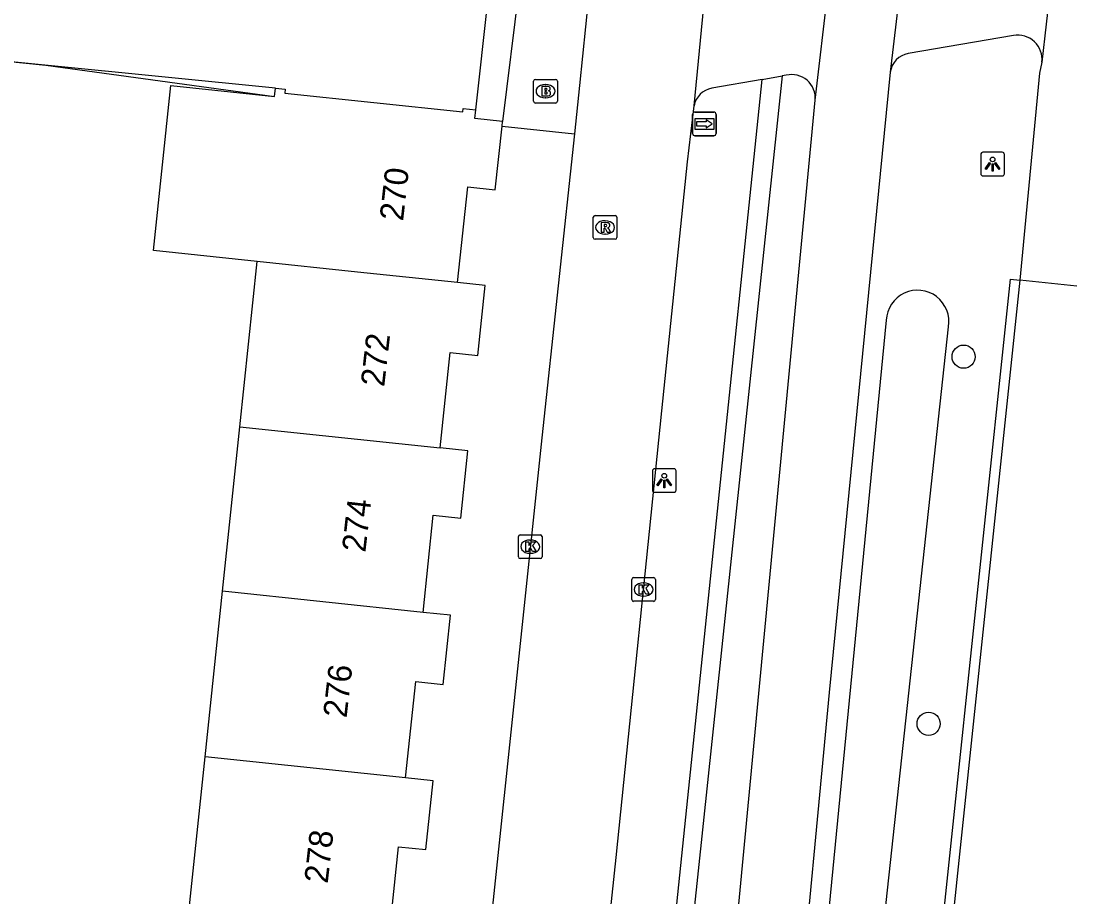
# Model space of a CAD drawing. Extents: x 161486 to 162249, y 379484 to 380829.
# Drawn here: x 162192.42 to 162236.98, y 380606.39 to 380643.33 of the extents above; entities that cross this region are included whole.
import ezdxf

# ---------------------------------------------------------------- set-up
doc = ezdxf.new("R2010")
doc.units = 0
for name, color, linetype in [('IMGEO_Berm_open', 7, 'Continuous'), ('IMGEO_Boom', 7, 'Continuous'), ('IMGEO_Brandkraan', 7, 'Continuous'), ('IMGEO_Fietspad_gesloten', 7, 'Continuous'), ('IMGEO_Fietspad_open', 7, 'Continuous'), ('IMGEO_Haag', 7, 'Continuous'), ('IMGEO_Kolk', 7, 'Continuous'), ('IMGEO_Lichtpunt', 7, 'Continuous'), ('IMGEO_Muur', 7, 'Continuous'), ('IMGEO_Pand', 7, 'Continuous'), ('IMGEO_Pand_nummerreeks', 7, 'Continuous'), ('IMGEO_Rijbaan_lokaal_gesloten', 7, 'Continuous'), ('IMGEO_Rijbaan_lokaal_open', 7, 'Continuous'), ('IMGEO_Rioolput', 7, 'Continuous'), ('IMGEO_Voetpad_open', 7, 'Continuous'), ('IMGEO_Waterloop', 7, 'Continuous'), ('IMGEO_Wegwijzer', 7, 'Continuous')]:
    doc.layers.add(name, color=color, linetype=linetype)

msp = doc.modelspace()

# ---------------------------------------------------------------- linework, layer by layer
at = {"layer": 'IMGEO_Berm_open'}
msp.add_lwpolyline([(162234.885, 380513.834), (162234.485, 380513.815), (162233.282, 380522.077), (162233.255, 380522.263), (162230.376, 380540.774), (162229.367, 380548.085), (162228.73, 380555.438), (162228.472, 380564.942), (162228.634, 380574.447), (162229.215, 380583.936), (162230.258, 380595.154), (162234.178, 380632.445), (162234.565, 380632.408)], dxfattribs=at)
at = {"layer": 'IMGEO_Boom'}
for centre in [(162232.199, 380629.179), (162230.723, 380613.693)]:
    msp.add_circle(centre, 0.489, dxfattribs=at)
at = {"layer": 'IMGEO_Brandkraan'}
for p, q in [((162214.05, 380639.952), (162214.05, 380640.804)), ((162214.125, 380640.878), (162214.977, 380640.878)), ((162214.538, 380640.658), (162214.563, 380640.658)), ((162215.051, 380640.804), (162215.051, 380639.952)), ((162214.977, 380639.878), (162214.125, 380639.878)), ((162214.561, 380640.098), (162214.536, 380640.098))]:
    msp.add_line(p, q, dxfattribs=at)
for points in [[(162214.05, 380639.952), (162214.05, 380640.804)], [(162214.125, 380640.878), (162214.977, 380640.878)], [(162214.398, 380640.578), (162214.398, 380640.178), (162214.611, 380640.178)], [(162214.629, 380640.578), (162214.398, 380640.578)], [(162215.051, 380640.804), (162215.051, 380639.952)], [(162214.577, 380640.497), (162214.523, 380640.497), (162214.523, 380640.421)], [(162214.523, 380640.421), (162214.576, 380640.421)], [(162214.585, 380640.345), (162214.523, 380640.345), (162214.523, 380640.264)], [(162214.523, 380640.264), (162214.585, 380640.264)], [(162214.977, 380639.878), (162214.125, 380639.878)]]:
    msp.add_lwpolyline(points, dxfattribs=at)
for centre, radius, start, end in [((162214.127, 380640.802), 0.0765, 91.552, 178.448), ((162214.127, 380640.802), 0.0765, 91.552, 178.448), ((162214.633, 380640.433), 0.145, 59.4692, 91.5367), ((162214.975, 380640.802), 0.0765, 1.552, 88.448), ((162214.975, 380640.802), 0.0765, 1.552, 88.448), ((162214.578, 380640.459), 0.0379, 267.8285, 90.9355), ((162214.586, 380640.304), 0.0404, 269.8759, 90.5077), ((162214.617, 380640.429), 0.251, 268.6676, 293.5347), ((162214.658, 380640.48), 0.0922, 285.5137, 58.1501), ((162214.663, 380640.288), 0.105, 301.3115, 78.989), ((162214.127, 380639.954), 0.0765, 181.552, 268.448), ((162214.127, 380639.954), 0.0765, 181.552, 268.448), ((162214.975, 380639.954), 0.0765, 271.552, 358.448), ((162214.975, 380639.954), 0.0765, 271.552, 358.448)]:
    msp.add_arc(centre, radius, start, end, dxfattribs=at)
for centre, major_axis, ratio, start_param, end_param in [((162214.537, 380640.378), (-0.387, 0.002), 0.722429, 4.712389, 7.853982), ((162214.562, 380640.378), (-0.39, 0.002), 0.717154, 1.570796, 4.712389)]:
    msp.add_ellipse(centre, major_axis=major_axis, ratio=ratio, start_param=start_param, end_param=end_param, dxfattribs=at)
at = {"layer": 'IMGEO_Fietspad_gesloten'}
for points in [[(162229.656, 380645.947), (162229.101, 380641.182)], [(162225.936, 380639.994), (162226.483, 380644.682)], [(162229.101, 380641.182), (162226.52, 380615.007), (162223.737, 380585.536)], [(162220.785, 380585.791), (162225.936, 380639.994)]]:
    msp.add_lwpolyline(points, dxfattribs=at)
at = {"layer": 'IMGEO_Fietspad_open'}
for points in [[(162234.304, 380642.732), (162229.862, 380641.971)], [(162223.699, 380640.873), (162224.538, 380641.02)], [(162224.713, 380641.051), (162224.538, 380641.02)], [(162223.699, 380640.873), (162221.566, 380640.501)]]:
    msp.add_lwpolyline(points, dxfattribs=at)
for centre, radius, start, end in [((162234.48, 380641.714), 1.033, 353.8878, 99.7979), ((162230.04, 380641.038), 0.95, 100.8127, 171.2572), ((162224.946, 380640.085), 0.994, 354.7527, 103.5756), ((162221.732, 380639.586), 0.93, 100.3017, 169.0038)]:
    msp.add_arc(centre, radius, start, end, dxfattribs=at)
at = {"layer": 'IMGEO_Haag'}
msp.add_lwpolyline([(162224.538, 380641.02), (162216.272, 380562.775), (162215.601, 380562.731), (162223.699, 380640.873)], dxfattribs=at)
at = {"layer": 'IMGEO_Kolk'}
for p, q in [((162213.406, 380620.738), (162213.406, 380621.59)), ((162213.481, 380621.664), (162214.333, 380621.664)), ((162213.894, 380621.444), (162213.919, 380621.444)), ((162214.407, 380621.59), (162214.407, 380620.738)), ((162214.333, 380620.664), (162213.481, 380620.664)), ((162213.917, 380620.884), (162213.892, 380620.884)), ((162218.188, 380618.932), (162218.188, 380619.784)), ((162218.263, 380619.858), (162219.115, 380619.858)), ((162218.676, 380619.638), (162218.701, 380619.638)), ((162219.189, 380619.784), (162219.189, 380618.932)), ((162219.115, 380618.858), (162218.263, 380618.858)), ((162218.699, 380619.078), (162218.674, 380619.078))]:
    msp.add_line(p, q, dxfattribs=at)
for points in [[(162213.406, 380620.738), (162213.406, 380621.59)], [(162213.481, 380621.664), (162214.333, 380621.664)], [(162214.407, 380621.59), (162214.407, 380620.738)], [(162213.727, 380621.364), (162213.85, 380621.364), (162213.85, 380621.213), (162213.98, 380621.364), (162214.144, 380621.364), (162213.998, 380621.213), (162214.151, 380620.964), (162213.999, 380620.964), (162213.914, 380621.128), (162213.85, 380621.061), (162213.85, 380620.964), (162213.727, 380620.964), (162213.727, 380621.364)], [(162214.333, 380620.664), (162213.481, 380620.664)], [(162218.188, 380618.932), (162218.188, 380619.784)], [(162218.263, 380619.858), (162219.115, 380619.858)], [(162219.189, 380619.784), (162219.189, 380618.932)], [(162218.509, 380619.558), (162218.632, 380619.558), (162218.632, 380619.407), (162218.762, 380619.558), (162218.926, 380619.558), (162218.78, 380619.407), (162218.933, 380619.158), (162218.781, 380619.158), (162218.696, 380619.322), (162218.632, 380619.255), (162218.632, 380619.158), (162218.509, 380619.158), (162218.509, 380619.558)], [(162219.115, 380618.858), (162218.263, 380618.858)]]:
    msp.add_lwpolyline(points, dxfattribs=at)
for centre, start, end in [((162213.483, 380621.588), 91.552, 178.448), ((162213.483, 380621.588), 91.552, 178.448), ((162214.331, 380621.588), 1.552, 88.448), ((162214.331, 380621.588), 1.552, 88.448), ((162213.483, 380620.74), 181.552, 268.448), ((162213.483, 380620.74), 181.552, 268.448), ((162214.331, 380620.74), 271.552, 358.448), ((162214.331, 380620.74), 271.552, 358.448), ((162218.265, 380619.782), 91.552, 178.448), ((162218.265, 380619.782), 91.552, 178.448), ((162219.113, 380619.782), 1.552, 88.448), ((162219.113, 380619.782), 1.552, 88.448), ((162218.265, 380618.934), 181.552, 268.448), ((162218.265, 380618.934), 181.552, 268.448), ((162219.113, 380618.934), 271.552, 358.448), ((162219.113, 380618.934), 271.552, 358.448)]:
    msp.add_arc(centre, 0.0765, start, end, dxfattribs=at)
for centre, major_axis, ratio, start_param, end_param in [((162213.893, 380621.164), (-0.387, 0.002), 0.722429, 4.712389, 7.853982), ((162213.918, 380621.164), (-0.39, 0.002), 0.717154, 1.570796, 4.712389), ((162218.675, 380619.358), (-0.387, 0.002), 0.722429, 4.712389, 7.853982), ((162218.7, 380619.358), (-0.39, 0.002), 0.717154, 1.570796, 4.712389)]:
    msp.add_ellipse(centre, major_axis=major_axis, ratio=ratio, start_param=start_param, end_param=end_param, dxfattribs=at)
at = {"layer": 'IMGEO_Lichtpunt'}
for p, q in [((162232.923, 380637.705), (162232.923, 380636.898)), ((162232.923, 380637.705), (162232.923, 380636.898)), ((162233.825, 380637.8), (162233.017, 380637.8)), ((162233.825, 380637.8), (162233.017, 380637.8)), ((162233.919, 380636.898), (162233.919, 380637.705)), ((162233.919, 380636.898), (162233.919, 380637.705)), ((162233.017, 380636.804), (162233.825, 380636.804)), ((162233.017, 380636.804), (162233.825, 380636.804)), ((162219.064, 380624.358), (162219.064, 380623.551)), ((162219.064, 380624.358), (162219.064, 380623.551)), ((162219.966, 380624.453), (162219.158, 380624.453)), ((162219.966, 380624.453), (162219.158, 380624.453)), ((162220.06, 380623.551), (162220.06, 380624.358)), ((162220.06, 380623.551), (162220.06, 380624.358)), ((162219.158, 380623.457), (162219.966, 380623.457)), ((162219.158, 380623.457), (162219.966, 380623.457))]:
    msp.add_line(p, q, dxfattribs=at)
for points in [[(162233.297, 380637.369), (162233.336, 380637.341), (162233.148, 380637.079), (162233.11, 380637.106), (162233.297, 380637.369)], [(162233.399, 380637.321), (162233.446, 380637.321), (162233.446, 380636.999), (162233.399, 380636.999), (162233.399, 380637.321)], [(162233.509, 380637.341), (162233.547, 380637.368), (162233.734, 380637.106), (162233.695, 380637.078), (162233.509, 380637.341)], [(162219.438, 380624.022), (162219.477, 380623.994), (162219.289, 380623.732), (162219.251, 380623.759), (162219.438, 380624.022)], [(162219.54, 380623.974), (162219.587, 380623.974), (162219.587, 380623.652), (162219.54, 380623.652), (162219.54, 380623.974)], [(162219.65, 380623.994), (162219.688, 380624.021), (162219.875, 380623.759), (162219.836, 380623.731), (162219.65, 380623.994)]]:
    msp.add_lwpolyline(points, dxfattribs=at)
for centre in [(162233.422, 380637.503), (162219.563, 380624.156)]:
    msp.add_circle(centre, 0.0994, dxfattribs=at)
for centre, start, end in [((162233.017, 380637.705), 90, 180), ((162233.017, 380637.705), 90, 180), ((162233.825, 380637.705), 0, 90), ((162233.825, 380637.705), 0, 90), ((162233.017, 380636.898), 180, 270), ((162233.017, 380636.898), 180, 270), ((162233.825, 380636.898), 270, 0), ((162233.825, 380636.898), 270, 360), ((162219.158, 380624.358), 90, 180), ((162219.158, 380624.358), 90, 180), ((162219.966, 380624.358), 0, 90), ((162219.966, 380624.358), 0, 90), ((162219.158, 380623.551), 180, 270), ((162219.158, 380623.551), 180, 270), ((162219.966, 380623.551), 270, 0), ((162219.966, 380623.551), 270, 360)]:
    msp.add_arc(centre, 0.0946, start, end, dxfattribs=at)
at = {"layer": 'IMGEO_Muur'}
msp.add_lwpolyline([(162186.682, 380638.42), (162186.829, 380640.299), (162188.729, 380641.957), (162193.454, 380641.474), (162203.113, 380640.152)], dxfattribs=at)
at = {"layer": 'IMGEO_Pand'}
for points in [[(162202.38, 380633.192), (162197.999, 380633.652), (162198.732, 380640.613), (162203.113, 380640.152), (162203.151, 380640.512)], [(162203.151, 380640.512), (162203.562, 380640.469), (162203.544, 380640.298), (162211.058, 380639.507), (162211.073, 380639.652), (162211.609, 380639.596)], [(162212.736, 380639.1), (162211.57, 380639.223), (162211.609, 380639.596)], [(162210.842, 380632.303), (162211.267, 380636.339), (162212.433, 380636.216), (162212.716, 380638.907)], [(162212.716, 380638.907), (162212.736, 380639.1)], [(162201.646, 380626.22), (162202.38, 380633.192)], [(162210.842, 380632.303), (162206.611, 380632.747), (162202.38, 380633.192)], [(162210.11, 380625.331), (162210.533, 380629.354), (162211.697, 380629.231), (162212.008, 380632.181), (162210.842, 380632.303)], [(162200.916, 380619.281), (162201.646, 380626.22)], [(162201.646, 380626.22), (162210.11, 380625.331)], [(162209.38, 380618.39), (162209.812, 380622.493), (162210.974, 380622.37), (162211.273, 380625.209), (162210.11, 380625.331)], [(162200.181, 380612.3), (162200.916, 380619.281)], [(162209.38, 380618.39), (162200.916, 380619.281)], [(162208.648, 380611.414), (162209.075, 380615.47), (162210.235, 380615.348), (162210.543, 380618.268), (162209.38, 380618.39)], [(162199.449, 380605.35), (162200.181, 380612.3)], [(162208.648, 380611.414), (162200.181, 380612.3)], [(162207.918, 380604.462), (162208.344, 380608.507), (162209.501, 380608.385), (162209.807, 380611.292), (162208.648, 380611.414)]]:
    msp.add_lwpolyline(points, dxfattribs=at)
at = {"layer": 'IMGEO_Rijbaan_lokaal_gesloten'}
msp.add_lwpolyline([(162234.565, 380632.408), (162230.654, 380595.209), (162229.611, 380583.991)], dxfattribs=at)
at = {"layer": 'IMGEO_Rijbaan_lokaal_open'}
for points in [[(162236.045, 380646.425), (162235.507, 380641.604)], [(162211.609, 380639.596), (162212.119, 380644.16)], [(162216.367, 380644.351), (162215.987, 380640.612), (162215.769, 380638.584)], [(162220.819, 380639.763), (162221.281, 380644.42)], [(162203.151, 380640.512), (162188.75, 380641.941), (162186.854, 380640.301), (162186.682, 380638.42)], [(162235.507, 380641.604), (162235.399, 380641.136), (162234.565, 380632.408)], [(162207.742, 380514.518), (162208.747, 380525.315), (162210.093, 380537.653), (162211.859, 380554.56), (162213.904, 380573.225), (162215.799, 380591.762), (162217.533, 380608.049), (162219.458, 380626.895), (162220.541, 380637.397), (162220.819, 380639.763)], [(162215.769, 380638.584), (162214.391, 380625.756), (162212.257, 380605.46), (162210.323, 380587.494), (162209.224, 380576.597)], [(162236.98, 380632.149), (162236.973, 380632.15), (162234.565, 380632.408)]]:
    msp.add_lwpolyline(points, dxfattribs=at)
at = {"layer": 'IMGEO_Rioolput'}
for p, q in [((162216.566, 380634.207), (162216.566, 380635.059)), ((162216.641, 380635.133), (162217.493, 380635.133)), ((162217.054, 380634.913), (162217.079, 380634.913)), ((162217.567, 380635.059), (162217.567, 380634.207)), ((162217.077, 380634.353), (162217.052, 380634.353)), ((162217.493, 380634.133), (162216.641, 380634.133))]:
    msp.add_line(p, q, dxfattribs=at)
for points in [[(162216.566, 380634.207), (162216.566, 380635.059)], [(162216.641, 380635.133), (162217.493, 380635.133)], [(162217.155, 380634.831), (162216.903, 380634.833), (162216.903, 380634.433)], [(162217.567, 380635.059), (162217.567, 380634.207)], [(162216.903, 380634.433), (162217.027, 380634.433), (162217.027, 380634.595), (162217.038, 380634.595)], [(162217.081, 380634.752), (162217.027, 380634.752), (162217.027, 380634.671)], [(162217.027, 380634.671), (162217.079, 380634.671)], [(162217.085, 380634.566), (162217.156, 380634.433), (162217.296, 380634.433), (162217.231, 380634.559)], [(162217.493, 380634.133), (162216.641, 380634.133)]]:
    msp.add_lwpolyline(points, dxfattribs=at)
for centre, radius, start, end in [((162216.643, 380635.057), 0.0765, 91.552, 178.448), ((162216.643, 380635.057), 0.0765, 91.552, 178.448), ((162217.154, 380634.721), 0.109, 350.3612, 89.416), ((162217.491, 380635.057), 0.0765, 1.552, 88.448), ((162217.491, 380635.057), 0.0765, 1.552, 88.448), ((162217.037, 380634.542), 0.0533, 26.0293, 88.6989), ((162217.063, 380634.86), 0.19, 274.7715, 282.9687), ((162217.087, 380634.656), 0.0964, 77.0061, 93.1865), ((162217.101, 380634.713), 0.0378, 276.6634, 79.6772), ((162217.152, 380634.721), 0.112, 277.5842, 350.9817), ((162217.136, 380634.506), 0.108, 29.5134, 73.7905), ((162216.643, 380634.209), 0.0765, 181.552, 268.448), ((162216.643, 380634.209), 0.0765, 181.552, 268.448), ((162217.491, 380634.209), 0.0765, 271.552, 358.448), ((162217.491, 380634.209), 0.0765, 271.552, 358.448)]:
    msp.add_arc(centre, radius, start, end, dxfattribs=at)
for centre, major_axis, ratio, start_param, end_param in [((162217.053, 380634.633), (-0.387, 0.002), 0.722429, 4.712389, 7.853982), ((162217.078, 380634.633), (-0.39, 0.002), 0.717154, 1.570796, 4.712389)]:
    msp.add_ellipse(centre, major_axis=major_axis, ratio=ratio, start_param=start_param, end_param=end_param, dxfattribs=at)
at = {"layer": 'IMGEO_Voetpad_open'}
for points in [[(162216.367, 380644.351), (162213.427, 380644.679), (162212.736, 380639.1)], [(162212.716, 380638.907), (162215.769, 380638.584)]]:
    msp.add_lwpolyline(points, dxfattribs=at)
at = {"layer": 'IMGEO_Waterloop'}
for points in [[(162228.933, 380630.72), (162225.474, 380595.156), (162224.306, 380581.587), (162224.277, 380581.251)], [(162226.337, 380573.015), (162226.805, 380582.401), (162227.735, 380595.12), (162231.557, 380630.432)]]:
    msp.add_lwpolyline(points, dxfattribs=at)
msp.add_arc((162230.254, 380630.661), 1.323, 350.018, 177.455, dxfattribs=at)
at = {"layer": 'IMGEO_Wegwijzer'}
for p, q in [((162220.76, 380638.599), (162220.76, 380639.399)), ((162220.76, 380639.399), (162220.76, 380638.599)), ((162220.86, 380639.499), (162221.65, 380639.499)), ((162221.65, 380639.499), (162220.86, 380639.499)), ((162221.75, 380639.399), (162221.75, 380638.599)), ((162221.75, 380638.599), (162221.75, 380639.399)), ((162221.65, 380638.499), (162220.86, 380638.499)), ((162220.86, 380638.499), (162221.65, 380638.499))]:
    msp.add_line(p, q, dxfattribs=at)
for points in [[(162220.861, 380639.231), (162221.649, 380639.231), (162221.649, 380638.767), (162220.861, 380638.767), (162220.861, 380639.231)], [(162220.926, 380639.083), (162220.926, 380638.999), (162220.926, 380638.915), (162221.337, 380638.915), (162221.337, 380638.832), (162221.584, 380638.999), (162221.337, 380639.166), (162221.337, 380639.083), (162220.926, 380639.083)]]:
    msp.add_lwpolyline(points, dxfattribs=at)
for centre, start, end in [((162220.86, 380639.399), 90, 180), ((162220.86, 380639.399), 90, 180), ((162221.65, 380639.399), 0, 90), ((162221.65, 380639.399), 360, 90), ((162220.86, 380638.599), 180, 270), ((162220.86, 380638.599), 180, 270), ((162221.65, 380638.599), 270, 0), ((162221.65, 380638.599), 270, 0)]:
    msp.add_arc(centre, 0.1, start, end, dxfattribs=at)

# ---------------------------------------------------------------- texts
at = {"layer": 'IMGEO_Pand_nummerreeks'}
for s, rotation, p in [('270', 83.5029, (162208.538, 380634.877)), ('272', 83.5029, (162207.742, 380627.885)), ('274', 83.5053, (162206.947, 380620.901)), ('276', 83.5053, (162206.152, 380613.915)), ('278', 83.5029, (162205.356, 380606.933))]:
    msp.add_text(s, height=1, rotation=rotation, dxfattribs=at).set_placement(p)

doc.saveas('drawing.dxf')
